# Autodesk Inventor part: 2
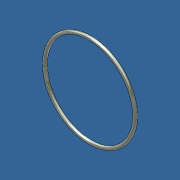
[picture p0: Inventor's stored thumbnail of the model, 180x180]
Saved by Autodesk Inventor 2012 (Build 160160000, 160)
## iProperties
Created: 2013-04
Part Number: 2
Material: Steel
Document SubType Name: Modeling
Designer: Admin
Density: 7.85 g/cm^3
Mass: 30.6807 g
Surface Area: 39.0836 cm^2
Volume: 3.90836 cm^3
Author: Admin
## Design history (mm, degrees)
node "21"
node "2"
node "Base1"
